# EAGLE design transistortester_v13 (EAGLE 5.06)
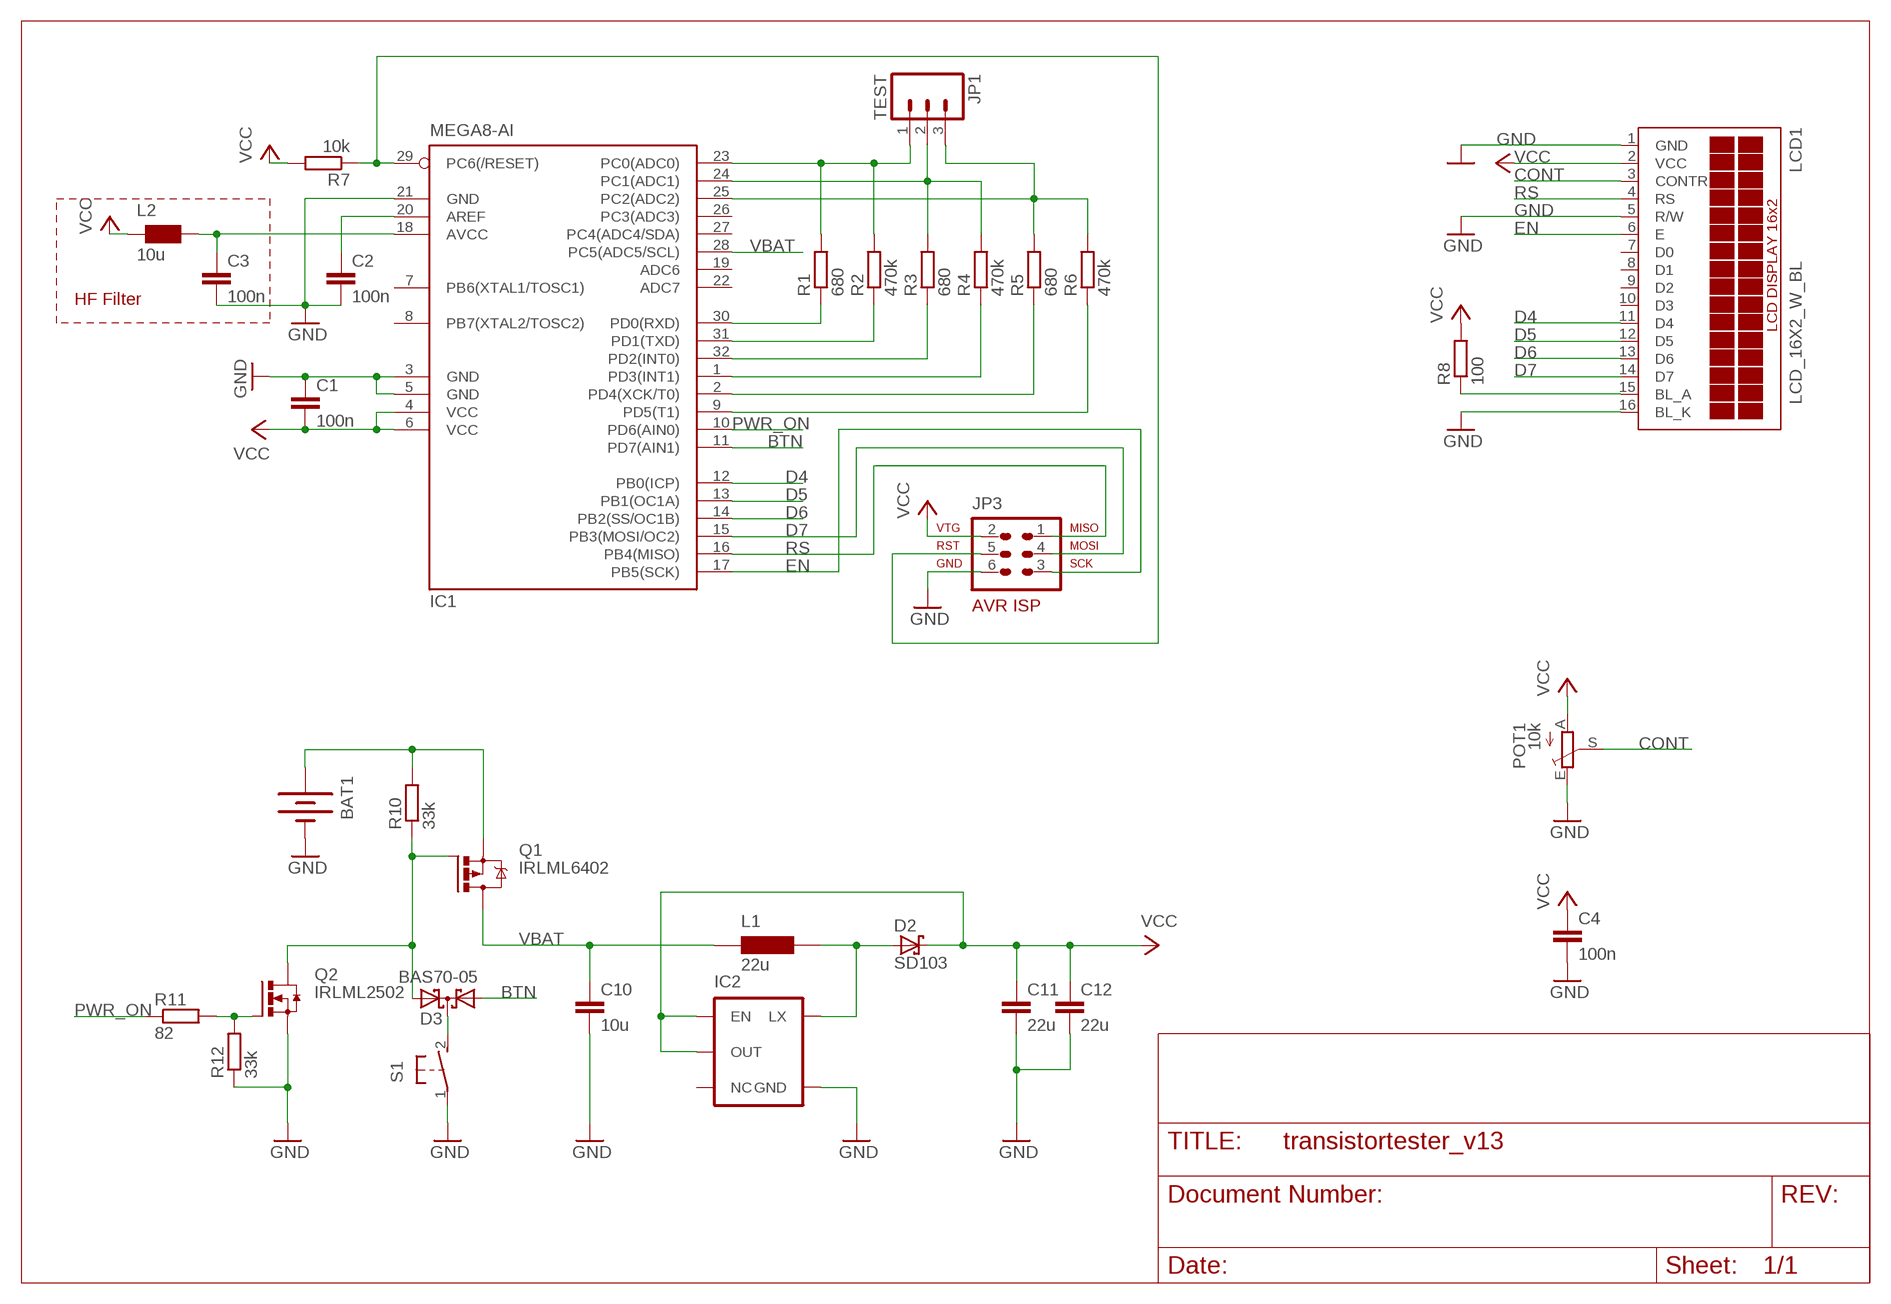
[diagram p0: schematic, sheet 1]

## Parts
BAT1  BATTERY-KEYSTONE_2AA  [BAT_KEYSTONE_2AA]
C1  100n  C-EUC0805K  [C0805K]
C2  100n  C-EUC0805K  [C0805K]
C3  100n  C-EUC0805K  [C0805K]
C4  100n  C-EUC0805K  [C0805K]
C10  10u  C-EUC1206  [C1206]
C11  22u  C-EUC1206  [C1206]
C12  22u  C-EUC1206  [C1206]
D2  SD103  SCHOTTKY-DIODESOD123  [SOD123]
D3  BAS70-05  [SOT23]
IC1  MEGA8-AI  [TQFP32-08]
IC2  V_REG_NCP1400SOT23-5  [SOT23-5]
JP1  TEST  M03LOCK_LONGPADS  [1X03_LOCK_LONGPADS]
JP3  AVR-ISP-6  [AVR-ISP-6]
L1  22u  LQH32CN  [1210]
L2  10u  WE-CBF_0805  [0805]
LCD1  LCD_16X2_W_BL  [LCD_16X2]
POT1  10k  TRIM_EU-CA6V  [CA6V]
Q1  IRLML6402  IRLML5203  [MICRO3]
Q2  IRLML2502  N-HEXFET_SOT23-IRLML2502  [SOT23]
R1  680  R-EU_R0805  [R0805]
R2  470k  R-EU_R0805  [R0805]
R3  680  R-EU_R0805  [R0805]
R4  470k  R-EU_R0805  [R0805]
R5  680  R-EU_R0805  [R0805]
R6  470k  R-EU_R0805  [R0805]
R7  10k  R-EU_R0805  [R0805]
R8  100  R-EU_R0805  [R0805]
R10  33k  R-EU_R0805  [R0805]
R11  82  R-EU_R0805  [R0805]
R12  33k  R-EU_R0805  [R0805]
S1  31-XX  [B3F-31XX]

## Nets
BTN: D3.1(A1) IC1.11(PD7(AIN1))
CONT: LCD1.3(CONTR) POT1.S
D4: IC1.12(PB0(ICP)) LCD1.11(D4)
D5: IC1.13(PB1(OC1A)) LCD1.12(D5)
D6: IC1.14(PB2(SS/OC1B)) LCD1.13(D6)
D7: IC1.15(PB3(MOSI/OC2)) JP3.4 LCD1.14(D7)
EN: IC1.17(PB5(SCK)) JP3.3 LCD1.6(E)
GND: BAT1.- C1.1 C2.2 C3.2 C4.2 C10.2 C11.2 C12.2 IC1.3(GND) IC1.5(GND) IC1.21(GND) IC2.4(GND) JP3.6 LCD1.1(GND) LCD1.5(R/W) LCD1.16(BL_K) POT1.E Q2.2(S) R12.1 S1.1(P)
N$1: IC1.30(PD0(RXD)) R1.1
N$2: IC1.31(PD1(TXD)) R2.1
N$3: IC1.32(PD2(INT0)) R3.1
N$4: IC1.1(PD3(INT1)) R4.1
N$5: IC1.2(PD4(XCK/T0)) R5.1
N$6: IC1.9(PD5(T1)) R6.1
N$7: C2.1 IC1.20(AREF)
N$8: IC1.23(PC0(ADC0)) JP1.1 R1.2 R2.2
N$9: IC1.24(PC1(ADC1)) JP1.2 R3.2 R4.2
N$10: IC1.25(PC2(ADC2)) JP1.3 R5.2 R6.2
N$11: LCD1.15(BL_A) R8.1
N$12: C3.1 IC1.18(AVCC) L2.2
N$13: Q2.1(G) R11.2 R12.2
N$14: IC1.29(PC6(/RESET)) JP3.5 R7.1
N$15: D3.3(C) S1.2(S)
N$17: BAT1.+ Q1.2(S) R10.2
N$25: D3.2(A2) Q1.1(G) Q2.3(D) R10.1
PWR_ON: IC1.10(PD6(AIN0)) R11.1
RS: IC1.16(PB4(MISO)) JP3.1 LCD1.4(RS)
VBAT: C10.1 IC1.28(PC5(ADC5/SCL)) L1.P$1 Q1.3(D)
VCC: C1.2 C4.1 C11.1 C12.1 D2.C IC1.4(VCC) IC1.6(VCC) IC2.1(EN) IC2.2(OUT) JP3.2 L2.1 LCD1.2(VCC) POT1.A R7.2 R8.2
VSW: D2.A IC2.5(LX) L1.P$2
Unconnected: IC1.7(PB6(XTAL1/TOSC1)) IC1.8(PB7(XTAL2/TOSC2)) IC1.19(ADC6) IC1.22(ADC7) IC1.26(PC3(ADC3)) IC1.27(PC4(ADC4/SDA)) IC2.3(NC) LCD1.7(D0) LCD1.8(D1) LCD1.9(D2) LCD1.10(D3)

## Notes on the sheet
- HF Filter

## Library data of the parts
BAT1 = ferdinandkeil:BATTERY-: BATTERY
C1-C4 C10-C12 = rcl:C-EU: CAPACITOR, European symbol
D2 = ferdinandkeil:SCHOTTKY-DIODE: Schottky Diode
D3 = diode:BAS70-05: Silicon Schottky Diodes General-purpose diode for high-speed switching
IC1 = atmel:MEGA8: MICROCONTROLLER 8 Kbytes FLASH, 1 kbytes SRAM, 512 bytes EEPROM, USART, 6-channel 10 bit ADC, 2-channel 8 bit ADC Pin compatible with Atmega48, ATMega88, ATMega168 Source: avr.lbr
IC2 = SparkFun:V_REG_NCP1400: Switching step-up voltage regulator NCP1400 switiching regulator takes single cell AA and outputs 100mA at 3.3V or 5V with minimal number of external components.
JP1 = SparkFun:M03: Header 3 Standard 3-pin 0.1" header. Use with straight break away headers (SKU : PRT-00116), right angle break away headers (PRT-00553), swiss pins (PRT-00743), machine pins (PRT-00117), and female headers (PRT-00115). Molex polarized connector foot print use with SKU : PRT-08232 with associated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
JP3 = avr-5:AVR-ISP-6: AVR ISP-6 Serial Programming Header
L1 = inductor-murata:LQH32CN: LQH32C - Power Inductor (Wire Wound Type for Choke)
L2 = wuerth-elektronik:WE-CBF: SMD EMI Suppression Ferrite Beads
LCD1 = ferdinandkeil:LCD_16X2_W_BL: LCD display 16x2 characters with backlight Source: tuxgr_12x2_r2.pdf Edited by ferdinandkeil@googlemail.com
POT1 = pot:TRIM_EU-: POTENTIOMETER
Q1 = transistor-power:IRLML5203: HEXFET P-Channel Power MOSFET
Q2 = ferdinandkeil:N-HEXFET_?-*: HEXFET® Power MOSFET
R1-R8 R10-R12 = rcl:R-EU_: RESISTOR, European symbol
S1 = switch-omron:31-XX: OMRON SWITCH

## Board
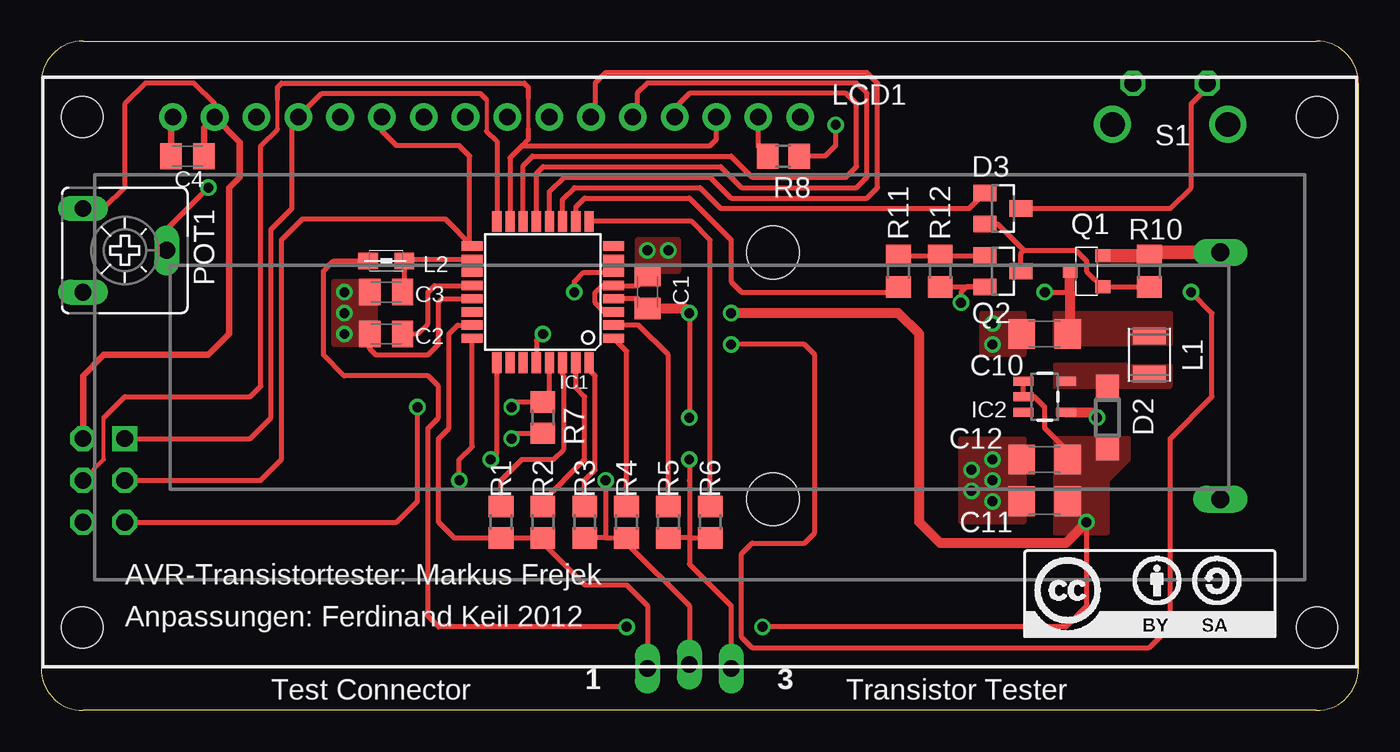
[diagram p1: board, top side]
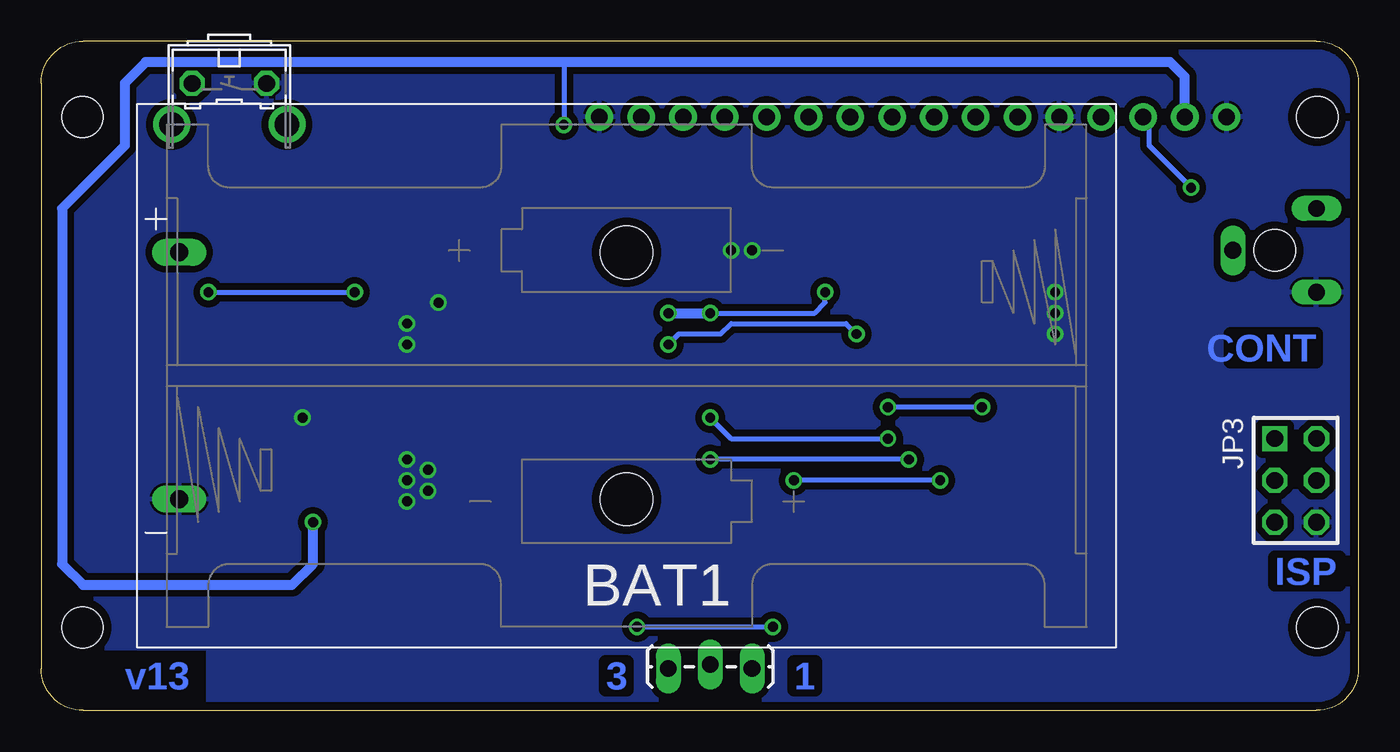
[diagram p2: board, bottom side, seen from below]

Size 80.01 x 40.64 mm. Coordinates in mm from the lower left corner, seen from the top.
Outline: 0,2.54 arc90 2.54,0 77.47,0 arc90 80.01,2.54 80.01,38.1 arc90 77.47,40.64 2.54,40.64 arc90 0,38.1 0,2.54
Copper layers (1*16): Top 0.035mm / dielectric 1.5mm / Bottom 0.035mm
Design rules "jakob_kleinen": minimum track width 0.15mm, minimum drill 0.3mm, track to track 0.15mm, track to pad 0.15mm, pad to pad 0.15mm, via to via 0.15mm, smd to smd 0.15mm, copper to edge 0.5mm, drill to drill 0.2mm, minimum pad ring 0.2mm, minimum via ring 0.2mm, stop-mask expansion 4mil, vias tented up to drill 0.8mm, thermal gap 0.15mm
Holes 2.5 mm at 5.08,27.94

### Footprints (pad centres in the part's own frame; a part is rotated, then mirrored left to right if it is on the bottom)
BAT_KEYSTONE_2AA = drill 1.1 long: + 27.178,-7.493; - 27.178,7.493 | hole 3.2: 0,7.493; 0,-7.493
C0805K = smd 1.3 x 1.6: 1 -1,0; 2 1,0
C1206 = smd 1.6 x 1.8: 1 -1.4,0; 2 1.4,0
SOD123 = smd 1.4 x 1.4: A 1.9,0; C -1.9,0
SOT23 = smd 1 x 1.4: 1 -0.95,-1.1; 2 0.95,-1.1; 3 0,1.1
TQFP32-08 = smd 1.27 x 0.559: 1 -4.293,2.8; 2 -4.293,2; 3 -4.293,1.2; 4 -4.293,0.4; 5 -4.293,-0.4; 6 -4.293,-1.2; 7 -4.293,-2; 8 -4.293,-2.8; 17 4.293,-2.8; 18 4.293,-2; 19 4.293,-1.2; 20 4.293,-0.4; 21 4.293,0.4; 22 4.293,1.2; 23 4.293,2; 24 4.293,2.8 | smd 0.559 x 1.27: 9 -2.8,-4.293; 10 -2,-4.293; 11 -1.2,-4.293; 12 -0.4,-4.293; 13 0.4,-4.293; 14 1.2,-4.293; 15 2,-4.293; 16 2.8,-4.293; 25 2.8,4.293; 26 2,4.293; 27 1.2,4.293; 28 0.4,4.293; 29 -0.4,4.293; 30 -1.2,4.293; 31 -2,4.293; 32 -2.8,4.293
SOT23-5 = smd 0.55 x 1.2: 1 -0.95,-1.3; 2 0,-1.3; 3 0.95,-1.3; 4 0.95,1.3; 5 -0.95,1.3
1X03_LOCK_LONGPADS = drill 1.016 long: 1 0,0; 2 2.54,-0.254; 3 5.08,0
AVR-ISP-6 = drill 1.016 square: 1 -2.54,-1.27 | drill 1.016 octagon: 2 -2.54,1.27; 3 0,-1.27; 4 0,1.27; 5 2.54,-1.27; 6 2.54,1.27
1210 = smd 1 x 2: P$1 -1.15,0; P$2 1.15,0
0805 = smd 1.2 x 1: 1 -1.1,0; 2 1.1,0
LCD_16X2 = drill 1 pad 1.676 round: 1 8,33.5; 2 10.54,33.5; 3 13.08,33.5; 4 15.62,33.5; 5 18.16,33.5; 6 20.7,33.5; 7 23.24,33.5; 8 25.78,33.5; 9 28.32,33.5; 10 30.86,33.5; 11 33.4,33.5; 12 35.94,33.5; 13 38.48,33.5; 14 41.02,33.5; 15 43.56,33.5; 16 46.1,33.5 | hole 2.5: 2.5,2.5; 77.5,2.5; 2.5,33.5; 77.5,33.5
CA6V = drill 1.016 long: A -2.54,-2.54; E 2.54,-2.54; S 0,2.54
MICRO3 = smd 0.8 x 0.9: 1 -0.95,-1; 2 0.95,-1; 3 0,1
R0805 = smd 1.3 x 1.5: 1 -0.95,0; 2 0.95,0
B3F-31XX = drill 1.016 octagon: 1 -2.261,-1.245; 2 2.261,-1.245 | drill 1.499 pad 2.159 round: 3 -3.505,1.245; 4 3.505,1.245

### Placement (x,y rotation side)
BAT1  44.45,20.32 180 bottom
C1  36.83,25.4 270 top
C2  20.95,22.86 180 top
C3  20.95,25.4 180 top
C4  8.89,33.66 180 top
C10  60.96,22.86 180 top
C11  60.96,12.7 180 top
C12  60.96,15.24 180 top
D2  64.77,17.78 90 top
D3  58.42,30.48 270 top
IC1  30.48,25.4 180 top
IC2  60.96,19.05 270 top
JP1  36.83,2.54 180 bottom
JP3  3.81,13.97 270 bottom
L1  67.31,21.59 270 top
L2  20.95,27.3 0 top
LCD1  0,2.54 0 top
POT1  5.08,27.94 270 top
Q1  63.5,26.67 90 top
Q2  58.42,26.67 270 top
R1  27.94,11.43 270 top
R2  30.48,11.43 270 top
R3  33.02,11.43 270 top
R4  35.56,11.43 270 top
R5  38.1,11.43 270 top
R6  40.64,11.43 270 top
R7  30.48,17.78 270 top
R8  45.09,33.66 0 top
R10  67.31,26.67 90 top
R11  52.07,26.67 90 top
R12  54.61,26.67 90 top
S1  68.58,36.83 180 bottom
U$1  [CC-BY-SA]  59.69,4.45 0 top

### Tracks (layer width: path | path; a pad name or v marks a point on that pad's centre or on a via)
BTN
  Top 0.305: IC1.11 31.68,31.05 32.38,31.75 40.01,31.75 41.27,30.48 56.37,30.48 D3.1 57.47,31.43
CONT  (via drill 0.6)
  Top 0.305: POT1.S 7.62,29.21 v10.16,31.75
  Bottom 0.305: v10.16,31.75 12.7,34.29 12.7,35.66 LCD1.3
D4
  Top 0.305: IC1.12 30.88,31.52 31.75,32.38 40.64,32.38 41.91,31.11 50.16,31.11 50.8,31.75 50.8,38.1 50.16,38.73 34.29,38.73 33.66,38.1 33.66,36.3 LCD1.11
D5
  Top 0.305: IC1.13 30.08,32.62 30.48,33.02 41.27,33.02 42.55,31.75 49.53,31.75 50.16,32.38 50.16,37.47 49.53,38.1 36.83,38.1 36.2,37.47 36.2,36.3 LCD1.12
D6
  Top 0.305: IC1.14 29.28,33.09 29.84,33.66 41.91,33.66 43.18,32.38 48.9,32.38 49.53,33.02 49.53,36.83 48.9,37.47 39.37,37.47 38.73,36.83 38.73,36.3 LCD1.13
D7
  Top 0.254: JP3.4 3.81,15.24 3.81,17.78 | 14.35,35.31 14.35,37.08 | 29.59,37.21 29.59,35.31
  Top 0.305: LCD1.14 41.02,34.67 40.64,34.29 29.21,34.29 | IC1.15 28.48,33.56 29.21,34.29 | 3.81,17.78 5.08,19.05 12.7,19.05 13.34,19.68 13.34,34.29 14.35,35.31 | 14.35,37.08 14.35,37.85 14.61,38.1 29.34,38.1 29.59,37.85 29.59,37.21 | 29.59,35.31 29.59,34.67 29.21,34.29
EN
  Top 0.305: LCD1.6 20.7,35.18 21.59,34.29 25.4,34.29 26.04,33.66 26.04,28.35 IC1.17 | IC1.17 25.77,28.2 | JP3.3 13.34,13.97 14.61,15.24 14.61,28.57 15.88,29.84 24.54,29.84 IC1.17
GND  (via drill 0.6)
  Top 0.305: C1.1 36.23,25.8 IC1.5 34.05,25.8 33.66,25.4 33.66,24.77 34.29,24.13 34.7,24.13 IC1.3 | IC1.21 24.36,25 24.13,24.77 24.13,22.23 23.5,21.59 20.32,21.59 19.95,21.95 C2.2 | R12.1 Q2.2 56.2,25.72 55.88,25.4 v55.88,24.77
  Top 0.406: C4.2 7.89,35.93 LCD1.1
  Top 0.61: IC2.4 63.81,18.1 v64.14,17.78
  other vias: 36.83,27.94 38.1,27.94 18.41,25.4 18.41,24.13 18.41,22.86 57.78,15.24 56.52,14.61 57.78,13.97 57.78,12.7 56.52,13.34 57.78,22.23 57.78,23.5
  pour Bottom (isolate 0.406, rank 2): 0,40.64 79.8,40.64 79.8,0 77.47,0 77.47,3.81 69.85,3.81 69.85,0 0,0
  pour Top (no thermals): 36.2,28.57 36.2,26.67 38.73,26.67 38.73,28.57
  pour Top (no thermals): 20.32,26.04 17.78,26.04 17.78,22.23 20.32,22.23
  pour Top (no thermals): 59.69,16.51 59.69,11.43 55.88,11.43 55.88,16.51
  pour Top (no thermals): 59.69,24.13 59.69,21.59 57.15,21.59 57.15,24.13
N$1
  Top 0.305: R1.1 27.94,13.97 29.21,15.24 31.11,15.24 31.75,15.88 31.75,20.32 31.68,20.39 IC1.30
N$2
  Top 0.305: R2.1 30.48,12.7 33.02,15.24 33.02,19.05 32.48,19.59 IC1.31
N$3
  Top 0.305: 33.02,12.7 R3.1 33.02,13.97 33.66,14.61 33.66,20.32 33.28,20.7 IC1.32
N$4
  Top 0.305: R4.1 35.56,21.81 IC1.1
N$5
  Top 0.305: IC1.2 36.29,23.4 38.1,21.59 R5.1
N$6
  Top 0.305: IC1.9 39.52,29.69 40.64,28.57 R6.1
N$7
  Top 0.305: IC1.20 23.89,25.8 23.5,25.4 23.5,23.5 22.86,22.86 C2.1
N$8
  Top 0.305: IC1.23 25.3,23.4 24.77,22.86 24.77,17.14 24.13,16.51 24.13,11.43 25.08,10.48 R1.2 R2.2 30.48,10.16 33.02,7.62 35.56,7.62 36.83,6.35 JP1.1
N$9  (via drill 0.6)
  Top 0.305: 34.29,10.48 R3.2 | 34.29,10.48 R4.2 35.56,10.16 39.37,6.35 JP1.2 | IC1.24 26.19,16.03 25.4,15.24 v25.4,13.97 | v34.29,13.97 34.29,10.48
  Bottom 0.305: v25.4,13.97 v34.29,13.97
N$10  (via drill 0.6)
  Top 0.305: 39.37,10.48 R5.2 | 39.37,10.48 R6.2 | IC1.25 27.68,15.62 v27.3,15.24 | JP1.3 41.91,6.35 39.37,8.89 39.37,10.48 | 39.37,10.48 39.37,13.97 v39.37,15.24
  Bottom 0.305: v27.3,15.24 v39.37,15.24
N$11
  Top 0.305: LCD1.15 43.56,34.23 R8.1
N$12
  Top 0.305: IC1.18 22.15,27.4 L2.2 22.05,25.5 C3.1
N$13
  Top 0.305: R12.2 R11.2 Q2.1
N$14  (via drill 0.6)
  Top 0.305: IC1.29 30.88,19.13 R7.1 28.89,18.73 v28.57,18.41 | JP3.5 21.59,11.43 22.86,12.7 v22.86,18.41
  Bottom 0.305: v22.86,18.41 v28.57,18.41
N$15
  Top 0.305: S1.2 70.84,37.82 69.85,36.83 69.85,31.75 68.58,30.48 D3.3
N$17
  Top 0.813: BAT1.+ 67.5,27.81 R10.2 Q1.2
N$25
  Top 0.305: R10.1 Q1.1 64.45,25.72 63.5,26.67 63.5,27.3 62.87,27.94 59.69,27.94 | D3.2 58.1,29.53 59.69,27.94 | Q2.3 59.52,27.77 59.69,27.94
PWR_ON
  Top 0.305: IC1.10 32.48,30.57 33.02,31.11 39.37,31.11 41.91,28.57 41.91,26.04 42.55,25.4 51.75,25.4 R11.1
RS
  Top 0.254: 27.05,37.08 27.05,35.18
  Top 0.305: IC1.16 27.68,34.55 27.05,35.18 | 27.05,37.08 26.67,37.47 17.05,37.47 LCD1.4 15.24,35.66 15.24,30.48 13.97,29.21 13.97,17.78 12.7,16.51 JP3.1
VBAT  (via drill 0.6)
  Top 0.305: IC1.28 30.08,22.46 v30.48,22.86 | v41.91,22.23 46.35,22.23 46.99,21.59 46.99,10.79 46.35,10.16 43.18,10.16 42.55,9.53 42.55,4.45 43.18,3.81 67.31,3.81 68.58,5.08 68.58,16.51 71.12,19.05 71.12,24.13 v69.85,25.4 | v60.96,25.4 62.5,25.4
  Top 0.61: Q1.3 62.5,25.4 62.5,23 C10.1
  Bottom 0.305: v30.48,22.86 31.11,23.5 38.1,23.5 38.73,22.86 41.27,22.86 v41.91,22.23 | v69.85,25.4 v60.96,25.4
  pour Top (no thermals): 68.58,22.23 61.59,22.23 61.59,24.13 68.58,24.13
VCC  (via drill 0.6)
  Top 0.305: IC1.4 36.23,25 C1.2 37.2,24.4 | IC2.1 IC2.2 60.33,19.05 60.96,18.41 60.96,17.14 62.23,15.88 62.23,15.37 C12.1 | R7.2 28.89,16.83 v28.57,16.51 | v39.37,24.13 v39.37,17.78 | IC1.6 32.95,26.6 32.38,26.04 v32.38,25.4 | POT1.A 3.81,30.48 5.08,31.75 5.08,36.83 6.35,38.1 9.27,38.1 10.54,36.83 LCD1.2 | L2.1 17.78,27.3 17.14,26.67 17.14,21.59 18.41,20.32 23.5,20.32 24.13,19.68 24.13,17.78 23.5,17.14 23.5,5.71 24.13,5.08 v35.56,5.08 | R8.2 47.62,33.66 48.26,34.29 v48.26,35.56 | v43.81,5.08 62.23,5.08 63.5,6.35 v63.5,11.43
  Top 0.406: C4.1 9.89,35.39 LCD1.2 12.06,34.52 12.06,32.38 11.43,31.75 11.43,22.86 10.16,21.59 3.81,21.59 2.54,20.32 JP3.2
  Top 0.61: 37.2,24.4 39.1,24.4 v39.37,24.13 | v41.91,24.13 52.07,24.13 53.34,22.86 53.34,11.43 54.61,10.16 62.23,10.16 v63.5,11.43
  Bottom 0.305: v28.57,16.51 38.1,16.51 v39.37,17.78 | v32.38,25.4 32.38,24.77 33.02,24.13 v39.37,24.13 | 48.26,39.37 v48.26,35.56 | v43.81,5.08 v35.56,5.08
  Bottom 0.61: v41.91,24.13 v39.37,24.13 | LCD1.2 10.54,38.48 11.43,39.37 48.26,39.37 73.66,39.37 74.93,38.1 74.93,34.29 78.74,30.48 78.74,8.89 77.47,7.62 64.77,7.62 63.5,8.89 v63.5,11.43
  pour Top (no thermals): 66.04,16.51 61.59,16.51 61.59,10.79 64.77,10.79 64.77,13.97 66.04,15.24
VSW
  pour Top (no thermals): 68.58,20.95 61.59,20.95 61.59,19.68 68.58,19.68

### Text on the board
Bottom: CONT | ISP | 1 | 3 | v13
tPlace: AVR-Transistortester: Markus Frejek | Anpassungen: Ferdinand Keil 2012 | 3 | Test Connector | 1 | Transistor Tester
